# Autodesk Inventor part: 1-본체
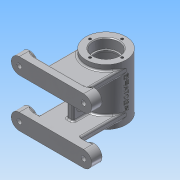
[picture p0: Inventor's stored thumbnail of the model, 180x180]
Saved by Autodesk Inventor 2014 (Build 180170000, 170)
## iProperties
Created: 2015-11
Part Number: 1-본체
Material: 알루미늄 6061
Document SubType Name: Modeling
Designer: 103-17
Density: 2.71 g/cm^3
Appearance: 알루미늄 - 평지
Mass: 359.139 g
Surface Area: 459.815 cm^2
Volume: 132.523 cm^3
Author: 103-17
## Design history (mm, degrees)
sketch "스케치1"
  geometry: C1 r 25 at (0, 0); 1 further point
  constraints: 1 centre point, 1 coincident
  dimensions: "d0" = 50 diameter of C1
extrude "돌출1" new body sketch "스케치1" stored distance "d1" = 70; taper "d2" = 0 deg
node "작업 평면1"
sketch "스케치2"
  geometry: L1 (-25, -35)-(25, -35) reference; L2 (25, 35)-(-25, 35) reference; L3 (-40, 40)-(40, 40); L4 (40, 20)-(-40, 20); L5 (-40, -20)-(40, -20); L6 (-40, -40)-(40, -40); A1 r 10 centre (-40, 30) between (-40, 40) and (-40, 20); A2 r 10 centre (40, 30) between (40, 40) and (40, 20); A3 r 10 centre (-40, -30) between (-40, -20) and (-40, -40); A4 r 10 centre (40, -30) between (40, -20) and (40, -40); 1 further point
  constraints: 8 end point, 8 point on circle, 5 tangent, 4 centre point, 3 equal radius, 2 horizontal, 2 horizontal alignment, 2 vertical alignment, 1 parallel
  dimensions: "d4" = 20 diameter of A1; "d5" = 80 distance of A2.centre A1.centre; "d6" = 40 horizontal distance of A1.centre point (0, 0); "d15" = 80 distance of L6.end L3.end; "d16" = 40 horizontal distance of L3.start point (0, 0)
  node "투영된 루프1"
extrude "돌출2" join sketch "스케치2" distance "d9" = 10; taper "d10" = 0 deg
extrude "돌출3" join sketch "스케치2" distance "d11" = 13; taper "d12" = 0 deg
sketch "스케치3"
  geometry: L1 (40, -20)-(-40, -20) reference; L2 (-40, 40)-(40, 40) reference; L3 (40, 20)-(-40, 20) reference; L4 (-25, 20)-(-25, 28); L5 (-25, 28)-(25, 28); L6 (25, 28)-(25, 20); L7 (-25, -20)-(-25, -28); L8 (-25, -28)-(25, -28); L9 (25, -28)-(25, -20); A1 r 10 centre (40, 30) between (40, 20) and (40, 40) reference; A2 r 10 centre (-40, 30) between (-40, 40) and (-40, 20) reference; 3 further points
  constraints: 12 end point, 5 perpendicular, 4 point on line, 2 equal length, 2 midpoint, 2 vertical alignment, 1 parallel
  dimensions: "d13" = 8 distance of L5.end L6.end; "d14" = 50 distance of L4.end L5.end
extrude "돌출4" join sketch "스케치3" stored distance "d17" = 13; taper "d18" = 0 deg
node "작업 평면2"
sketch "스케치4"
  geometry: L1 (25, -28)-(-25, -28) reference; L2 (-25, -28)-(-25, -20) reference; L3 (-25, -20)-(25, -20) reference; L4 (25, -20)-(25, -28) reference; L5 (-25, 28)-(25, 28) reference; L6 (25, 28)-(25, 20) reference; L7 (25, 20)-(-25, 20) reference; L8 (-25, 20)-(-25, 28) reference; L9 (-4, 20)-(-4, -20); L10 (4, 20)-(4, -20); 1 further point
  constraints: 4 end point, 4 point on line, 2 perpendicular
  dimensions: "d20" = 8 distance between parallel lines of L9 L10; "d21" = 4 distance from line of point (0, 0) L9
extrude "돌출5" join sketch "스케치4" stored distance "d22" = 8; taper "d23" = 0 deg
sketch "스케치5"
  geometry: L1 (0, 20.322)-(40, 20.322) reference; L2 (40, 20.322)-(40, 0) reference; L3 (12, 13.5)-(28, 13.5); L4 (28, 6.5)-(12, 6.5); L5 (40, -23)-(60, -23) reference; A1 r 3.5 centre (28, 10) between (28, 6.5) and (28, 13.5); A2 r 3.5 centre (12, 10) between (12, 13.5) and (12, 6.5); 3 further points
  constraints: 4 end point, 4 point on circle, 4 tangent, 2 centre point, 2 midpoint, 1 parallel, 1 perpendicular, 1 vertical alignment
  dimensions: "d24" = 23 dimension on A1 A2; "d25" = 3.5 radius of A1; "d26" = 33 distance from line of L5 A1.centre
extrude "돌출6" cut sketch "스케치5" stored distance "d27" = 0; taper "d28" = 0 deg
sketch "스케치6"
  geometry: C1 r 10 at (0, 0) reference; C2 r 10 at (0, -60) reference; C3 r 10 at (-80, -60) reference; C4 r 10 at (-80, 0) reference; 5 further points
  constraints: 4 coincident
hole "구멍1" sketch "스케치6" at (-80, 0), (0, 0), (0, -60), (-80, -60) diameter "d29" = 6; stored, may be unused: countersink angle "d33" = 90 deg, drill point angle "d35" = 118 deg; dims "d30" = 6, "d31" = 12, "d32" = 4, "d34" = 8
hole "구멍2" diameter "d38" = 28; stored, may be unused: countersink angle "d42" = 90 deg, drill point angle "d44" = 0 deg; dims "d39" = 6, "d40" = 32, "d41" = 12, "d43" = 14, "d45" = 10, "d46" = 10
hole "구멍3" diameter "d49" = 42; stored, may be unused: countersink angle "d53" = 90 deg, drill point angle "d55" = 0 deg; dims "d47" = 10, "d48" = 10, "d50" = 6, "d51" = 32, "d52" = 12, "d54" = 42
sketch "스케치7"
  geometry: C1 r 16 at (0, 0) reference; 1 further point
  constraints: 1 vertical alignment
  dimensions: "d56" = 20 distance of point (0, 20) C1.centre
hole "구멍4" sketch "스케치7" at (0, 20) diameter "d57" = 3.242; stored, may be unused: countersink angle "d61" = 90 deg, drill point angle "d63" = 118 deg; dims "d58" = 8, "d59" = 32, "d60" = 12, "d62" = 10
node "작업 평면3"
sketch "스케치8"
  geometry: C1 r 5 at (0, 0); 1 further point
  constraints: 1 centre point, 1 coincident
  dimensions: "d68" = 10 diameter of C1
extrude "돌출7" join sketch "스케치8" stored distance "d69" = 8; taper "d70" = 0 deg
node "작업 평면5"
  node "작업 평면4"
hole "구멍5" diameter "d78" = 5.188; stored, may be unused: countersink angle "d82" = 90 deg, drill point angle "d84" = 118 deg; dims "d76" = 10, "d77" = 10, "d79" = 8, "d80" = 32, "d81" = 12, "d83" = 10
node "작업 평면6"
sketch "스케치10"
  geometry: L1 (25, -35)-(25, 35) reference; L2 (25, 35)-(-25, 35) reference; 2 further points
  constraints: 1 other
  dimensions: "d95" = 35 distance from line of L2 point (0, 0); "d96" = 25 distance from line of L1 point (0, 0)
feature "엠보싱1" sketch "스케치10" dims "d0" = 50, "d97" = 0.5, "d98" = 0
fillet "모깎기1" dims "d99" = 3, "d100" = 0.3, "d101" = 2
fillet "모깎기2" dims "d102" = 2
fillet "모깎기3" dims "d103" = 2
fillet "모깎기4" dims "d104" = 2
chamfer "모따기1" distance "d105" = 1; stored, may be unused: second distance "d106" = 2, angle "d107" = 45 deg
node "작업 평면8"
  node "작업 평면7"
sketch "스케치11"
  geometry: C1 r 6 at (0, 0); 1 further point
  constraints: 1 centre point, 1 coincident
  dimensions: "d110" = 12 diameter of C1
extrude "돌출9" join sketch "스케치11" stored distance "d111" = 8; taper "d112" = 0 deg
hole "구멍7" diameter "d115" = 5.188; stored, may be unused: countersink angle "d119" = 90 deg, drill point angle "d121" = 0 deg; dims "d113" = 10, "d114" = 10, "d116" = 8, "d117" = 32, "d118" = 12, "d120" = 10
fillet "모깎기5" dims "d122" = 2
node "솔리드1"
mirror "대칭1"
pattern_circular "원형 패턴1" dims angle "d65" = 360 deg
mirror "대칭2"
node "투영된 루프2"
node "투영된 루프3"
node "투영된 루프4"
node "투영된 루프5"
node "절단 모서리 투영1"
other parameters: "d3" = -68, "d19" = -45, "d67" = 28, "d71" = 30 deg, "d72" = -28, "d94" = 49.25, "d108" = -30 deg, "d109" = -28
